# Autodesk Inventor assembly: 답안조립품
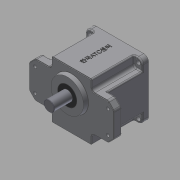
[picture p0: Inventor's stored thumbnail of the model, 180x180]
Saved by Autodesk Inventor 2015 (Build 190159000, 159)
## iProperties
Created: 2016-02
Part Number: 답안조립품
Document SubType Name: Assembly
Designer: Administrator
Author: Administrator
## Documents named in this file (10)
- C:\Users\Administrator\Desktop\460209V1008\답안조립품.iam
- C:\Users\Administrator\Desktop\460209V1008\본체.ipt
- C:\Users\Administrator\Desktop\460209V1008\커버.ipt
- C:\Users\Administrator\Desktop\460209V1008\오일실 8 22 7.ipt
- C:\Users\Administrator\Desktop\460209V1008\베어링 608.ipt
- C:\Users\Administrator\Desktop\460209V1008\메인축.ipt
- C:\Users\Administrator\Desktop\460209V1008\서브축.ipt
- C:\Users\Administrator\Desktop\460209V1008\베어링 6003.ipt
- C:\Users\Administrator\Desktop\460209V1008\오일실 17 32 8.ipt
- C:\Users\Administrator\Desktop\460209V1008\볼트 M4 x 10.ipt
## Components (2 placed, 1 different names)
1. ISO 4762 M4 x 10:1 — Insert:1
2. ISO 4762 M4 x 10:2 — Insert:2
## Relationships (2: Insert 2)
- Insert:1: ISO 4762 M4 x 10:1
- Insert:2: ISO 4762 M4 x 10:2
